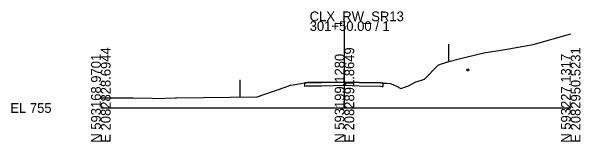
# Model space of a CAD drawing. Extents: x -26 to 2138, y -10 to 4518.
# Drawn here: x -25.7 to 137.8, y 490.3 to 527.8 of the extents above; entities that cross this region are included whole.
import ezdxf

# ---------------------------------------------------------------- set-up
doc = ezdxf.new("R2010")
doc.units = 0
for name, color, linetype in [('GK_Cells', 7, 'Continuous'), ('MD_X_Asphalt_Pavement', 7, 'Continuous'), ('RW_X_Esmt_SH', 7, 'Continuous'), ('UT_X_Water', 7, 'Continuous'), ('XS_X_Ground_Line', 7, 'Continuous')]:
    doc.layers.add(name, color=color, linetype=linetype)

msp = doc.modelspace()

# ---------------------------------------------------------------- linework, layer by layer
at = {"layer": 'GK_Cells'}
for p, q in [((70, 500), (70, 525)), ((0, 500), (70, 500)), ((70, 500), (135, 500))]:
    msp.add_line(p, q, dxfattribs=at)
at = {"layer": 'MD_X_Asphalt_Pavement'}
msp.add_lwpolyline([(58.99, 507.29), (58.47, 507.27), (58.47, 506.31), (58.99, 506.34), (59.35, 506.36), (63.43, 506.43), (70.18, 506.53), (74.22, 506.43), (80.45, 506.3), (80.86, 506.24), (81.09, 506.22), (81.09, 507.18), (80.86, 507.2), (80.45, 507.26), (74.22, 507.38), (70.18, 507.49), (63.43, 507.39), (59.35, 507.32), (58.99, 507.29)], dxfattribs=at)
at = {"layer": 'RW_X_Esmt_SH'}
for p, q in [((100, 513.4), (100, 518.4)), ((40, 503.16), (40, 508.16))]:
    msp.add_line(p, q, dxfattribs=at)
at = {"layer": 'UT_X_Water'}
msp.add_circle((105.43, 510.96), 0.3, dxfattribs=at)
at = {"layer": 'XS_X_Ground_Line'}
msp.add_lwpolyline([(0, 502.93), (0.94, 502.95), (3.02, 502.95), (7.41, 502.94), (9.3, 502.94), (14.85, 502.83), (15.55, 502.78), (21.32, 502.91), (21.74, 502.92), (44.89, 503.22), (53, 506.04), (54.47, 506.55), (55.3, 506.69), (58.47, 507.27), (58.99, 507.29), (59.35, 507.32), (63.43, 507.39), (70.18, 507.49), (74.22, 507.38), (80.45, 507.26), (80.86, 507.2), (81.09, 507.18), (82.03, 507.12), (83.19, 507.06), (84.9, 506.27), (86.16, 505.64), (86.75, 505.83), (87.22, 505.96), (88.36, 506.43), (90.29, 507.43), (92.98, 508.31), (96.9, 512.3), (97.28, 512.55), (99.42, 513.25), (99.48, 513.27), (99.64, 513.31), (103.29, 514.22), (108.76, 515.6), (110.01, 515.88), (114.89, 516.63), (117.23, 517.06), (124.25, 518.31), (135, 521.32)], dxfattribs=at)

# ---------------------------------------------------------------- texts
msp.add_text('-', height=0.0001).set_placement((0, 500))
at = {"layer": 'GK_Cells'}
for s, p in [('CLX_RW_SR13', (60, 525)), ('301+50.00 / 1', (60, 522.2)), ('EL 755', (-26, 498.6))]:
    msp.add_text(s, height=2.8, dxfattribs=at).set_placement(p)
for s, p in [('E 2082828.6944', (2.8, 490)), ('E 2082891.8649', (72.8, 490)), ('E 2082950.5231', (137.8, 490)), ('N 593168.9701', (0, 490)), ('N 593199.1280', (70, 490)), ('N 593227.1317', (135, 490))]:
    msp.add_text(s, height=2.8, rotation=90, dxfattribs=at).set_placement(p)

doc.saveas('drawing.dxf')
